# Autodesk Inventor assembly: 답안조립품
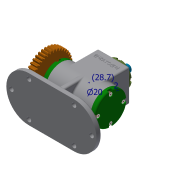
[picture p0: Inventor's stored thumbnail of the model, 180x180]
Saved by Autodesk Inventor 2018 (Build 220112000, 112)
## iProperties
Created: 2020-01
Part Number: 답안조립품
Document SubType Name: Assembly
Designer: Administrator
Mass: 2018.69 g
Surface Area: 1737.06 cm^2
Volume: 591.723 cm^3
Density: 3.41155 g/cm^3
Author: Administrator
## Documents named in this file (18)
- C:\Users\expoc\Desktop\600104V1042\답안조립품.iam
- C:\Users\expoc\Desktop\600104V1042\본체.ipt
- C:\Users\expoc\Desktop\600104V1042\베어링 6203.ipt
- C:\Users\expoc\Desktop\600104V1042\편심축.ipt
- C:\Users\expoc\Desktop\600104V1042\앞커버.ipt
- C:\Users\expoc\Desktop\600104V1042\뒤커버.ipt
- C:\Users\expoc\Desktop\600104V1042\상부커버.ipt
- C:\Users\expoc\Desktop\600104V1042\볼트 M4.ipt
- C:\Users\expoc\Desktop\600104V1042\오일 실 17 30 5.ipt
- C:\Users\expoc\Desktop\600104V1042\Ű 4x4x12.ipt
- C:\Users\expoc\Desktop\600104V1042\스퍼기어.ipt
- C:\Users\expoc\Desktop\600104V1042\스프링와셔.ipt
- C:\Users\expoc\Desktop\600104V1042\평와셔.ipt
- C:\Users\expoc\Desktop\600104V1042\부시.ipt
- C:\Users\expoc\Desktop\600104V1042\멈춤링.ipt
- C:\Users\expoc\Desktop\600104V1042\슬라이더.ipt
- C:\Users\expoc\Desktop\600104V1042\스프링조립용 와셔.ipt
- C:\Users\expoc\Desktop\600104V1042\가변스프링.ipt
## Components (2 placed, 2 different names)
1. Ű 4x4x12:1
2. 가변스프링:1
